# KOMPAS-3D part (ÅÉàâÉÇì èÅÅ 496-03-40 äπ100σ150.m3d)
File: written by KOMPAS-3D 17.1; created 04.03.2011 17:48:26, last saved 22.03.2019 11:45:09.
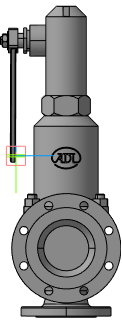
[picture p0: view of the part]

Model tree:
1. Плоскость XY
2. Плоскость ZX
3. Плоскость ZY
4. Ось X
5. Ось Y
6. Ось Z
7. Начало координат
8. Операция без истории:2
